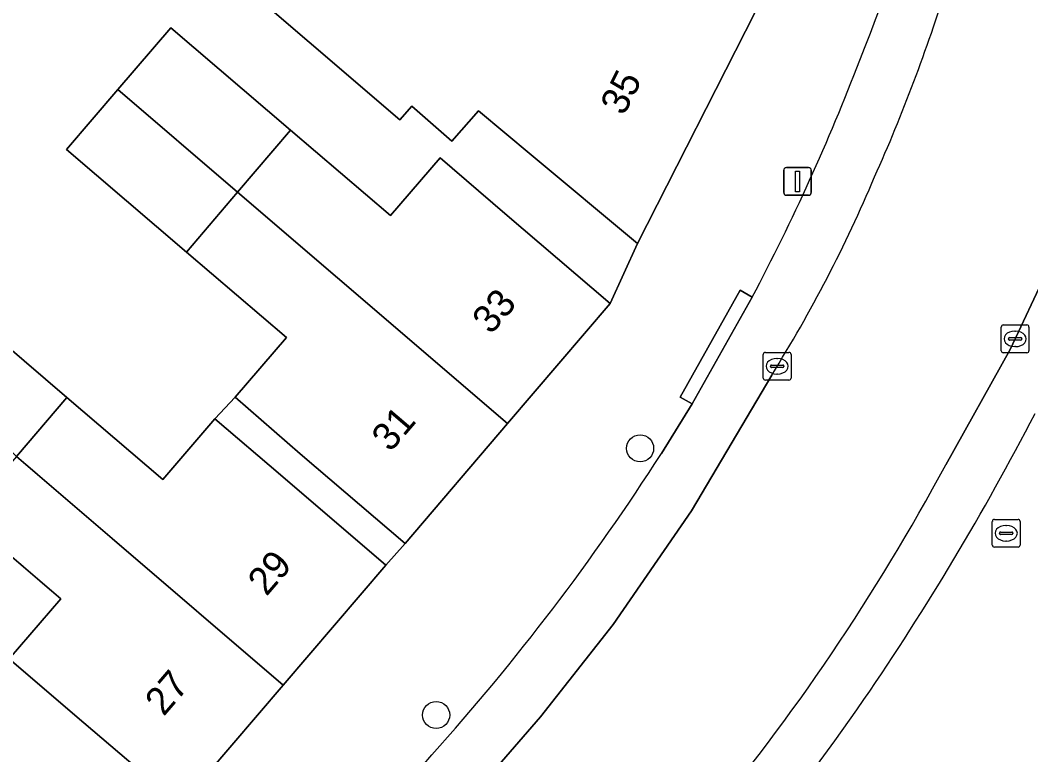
# Model space of a CAD drawing. Extents: x 162879 to 165540, y 384011 to 385181.
# Drawn here: x 164248.79 to 164285.23, y 384359.25 to 384385.74 of the extents above; entities that cross this region are included whole.
import ezdxf

# ---------------------------------------------------------------- set-up
doc = ezdxf.new("R2010")
doc.units = 0
for name, color, linetype in [('IMGEO_Boom', 7, 'Continuous'), ('IMGEO_Erf', 7, 'Continuous'), ('IMGEO_Kolk', 7, 'Continuous'), ('IMGEO_Lichtmast', 7, 'Continuous'), ('IMGEO_Pand', 7, 'Continuous'), ('IMGEO_Pand_nummerreeks', 7, 'Continuous'), ('IMGEO_Pand_overbouw', 7, 'Continuous'), ('IMGEO_Parkeervlak_open', 7, 'Continuous'), ('IMGEO_Rijbaan_lokaal_gesloten', 7, 'Continuous'), ('IMGEO_Rioolput', 7, 'Continuous'), ('IMGEO_Voetpad_open', 7, 'Continuous')]:
    doc.layers.add(name, color=color, linetype=linetype)

msp = doc.modelspace()

# ---------------------------------------------------------------- linework, layer by layer
at = {"layer": 'IMGEO_Boom'}
for centre in [(164271.145, 384370.303), (164263.79, 384360.686)]:
    msp.add_circle(centre, 0.489, dxfattribs=at)
at = {"layer": 'IMGEO_Erf'}
for points in [[(164247.382, 384374.782), (164250.477, 384372.133), (164253.93, 384369.178), (164255.809, 384371.373), (164258.178, 384369.345), (164261.977, 384366.094), (164262.667, 384366.877), (164258.888, 384370.111), (164256.543, 384372.144), (164258.388, 384374.301), (164254.784, 384377.384), (164250.465, 384381.078), (164252.316, 384383.243), (164254.223, 384385.472), (164258.542, 384381.777), (164262.145, 384378.695), (164263.93, 384380.782), (164266.271, 384378.778), (164270.07, 384375.527), (164271.057, 384377.691), (164267.216, 384380.891), (164265.32, 384382.471), (164264.358, 384381.377), (164262.911, 384382.649), (164262.476, 384382.154), (164236.314, 384404.571)], [(164246.201, 384348.47), (164248.925, 384351.39), (164254.565, 384357.434), (164250.766, 384360.685), (164248.397, 384362.714), (164250.251, 384364.881), (164246.799, 384367.836)]]:
    msp.add_lwpolyline(points, dxfattribs=at)
at = {"layer": 'IMGEO_Kolk'}
for p, q in [((164284.168, 384373.826), (164284.168, 384374.678)), ((164284.243, 384374.752), (164285.095, 384374.752)), ((164284.656, 384374.532), (164284.681, 384374.532)), ((164285.169, 384374.678), (164285.169, 384373.826)), ((164284.427, 384374.246), (164284.427, 384374.258)), ((164284.865, 384374.209), (164284.467, 384374.209)), ((164284.47, 384374.295), (164284.868, 384374.295)), ((164284.911, 384374.258), (164284.911, 384374.246)), ((164275.662, 384373.764), (164276.514, 384373.764)), ((164285.095, 384373.752), (164284.243, 384373.752)), ((164284.679, 384373.972), (164284.654, 384373.972)), ((164275.587, 384372.838), (164275.587, 384373.69)), ((164276.075, 384373.544), (164276.1, 384373.544)), ((164276.588, 384373.69), (164276.588, 384372.838)), ((164275.846, 384373.258), (164275.846, 384373.27)), ((164276.284, 384373.221), (164275.886, 384373.221)), ((164275.889, 384373.307), (164276.287, 384373.307)), ((164276.33, 384373.27), (164276.33, 384373.258)), ((164276.514, 384372.764), (164275.662, 384372.764)), ((164276.098, 384372.984), (164276.073, 384372.984))]:
    msp.add_line(p, q, dxfattribs=at)
for points in [[(164284.168, 384373.826), (164284.168, 384374.678)], [(164284.243, 384374.752), (164285.095, 384374.752)], [(164285.169, 384374.678), (164285.169, 384373.826)], [(164275.662, 384373.764), (164276.514, 384373.764)], [(164285.095, 384373.752), (164284.243, 384373.752)], [(164275.587, 384372.838), (164275.587, 384373.69)], [(164276.588, 384373.69), (164276.588, 384372.838)], [(164276.514, 384372.764), (164275.662, 384372.764)]]:
    msp.add_lwpolyline(points, dxfattribs=at)
for centre, radius, start, end in [((164284.245, 384374.676), 0.0765, 91.552, 178.448), ((164284.245, 384374.676), 0.0765, 91.552, 178.448), ((164285.093, 384374.676), 0.0765, 1.552, 88.448), ((164285.093, 384374.676), 0.0765, 1.552, 88.448), ((164284.467, 384374.255), 0.0403, 85.8775, 175.7526), ((164284.464, 384374.245), 0.0366, 178.938, 274.7102), ((164284.868, 384374.252), 0.043, 264.8664, 352.4533), ((164284.872, 384374.257), 0.0386, 1.7309, 96.639), ((164275.664, 384373.688), 0.0765, 91.552, 178.448), ((164275.664, 384373.688), 0.0765, 91.552, 178.448), ((164276.512, 384373.688), 0.0765, 1.552, 88.448), ((164276.512, 384373.688), 0.0765, 1.552, 88.448), ((164284.245, 384373.828), 0.0765, 181.552, 268.448), ((164284.245, 384373.828), 0.0765, 181.552, 268.448), ((164285.093, 384373.828), 0.0765, 271.552, 358.448), ((164285.093, 384373.828), 0.0765, 271.552, 358.448), ((164275.886, 384373.267), 0.0403, 85.8775, 175.7526), ((164275.883, 384373.257), 0.0366, 178.938, 274.7102), ((164276.287, 384373.264), 0.043, 264.8664, 352.4533), ((164276.291, 384373.269), 0.0386, 1.7309, 96.639), ((164275.664, 384372.84), 0.0765, 181.552, 268.448), ((164275.664, 384372.84), 0.0765, 181.552, 268.448), ((164276.512, 384372.84), 0.0765, 271.552, 358.448), ((164276.512, 384372.84), 0.0765, 271.552, 358.448)]:
    msp.add_arc(centre, radius, start, end, dxfattribs=at)
for centre, major_axis, ratio, start_param, end_param in [((164284.655, 384374.252), (-0.387, 0.002), 0.722429, 4.712389, 7.853982), ((164284.68, 384374.252), (-0.39, 0.002), 0.717154, 1.570796, 4.712389), ((164276.074, 384373.264), (-0.387, 0.002), 0.722429, 4.712389, 7.853982), ((164276.099, 384373.264), (-0.39, 0.002), 0.717154, 1.570796, 4.712389)]:
    msp.add_ellipse(centre, major_axis=major_axis, ratio=ratio, start_param=start_param, end_param=end_param, dxfattribs=at)
at = {"layer": 'IMGEO_Lichtmast'}
for p, q in [((164276.326, 384379.53), (164276.326, 384380.33)), ((164276.326, 384380.33), (164276.326, 384379.53)), ((164276.426, 384380.43), (164277.216, 384380.43)), ((164277.216, 384380.43), (164276.426, 384380.43)), ((164277.316, 384380.33), (164277.316, 384379.53)), ((164277.316, 384379.53), (164277.316, 384380.33)), ((164277.216, 384379.43), (164276.426, 384379.43)), ((164276.426, 384379.43), (164277.216, 384379.43))]:
    msp.add_line(p, q, dxfattribs=at)
msp.add_lwpolyline([(164276.746, 384380.305), (164276.896, 384380.305), (164276.896, 384379.555), (164276.746, 384379.555), (164276.746, 384380.305)], dxfattribs=at)
for centre, start, end in [((164276.426, 384380.33), 90, 180), ((164276.426, 384380.33), 90, 180), ((164277.216, 384380.33), 0, 90), ((164277.216, 384380.33), 360, 90), ((164276.426, 384379.53), 180, 270), ((164276.426, 384379.53), 180, 270), ((164277.216, 384379.53), 270, 0), ((164277.216, 384379.53), 270, 0)]:
    msp.add_arc(centre, 0.1, start, end, dxfattribs=at)
at = {"layer": 'IMGEO_Pand'}
for points in [[(164256.673, 384395.931), (164250.35, 384399.543), (164250.13, 384401.017), (164250.096, 384401.244), (164247.628, 384400.874), (164246.84, 384406.136), (164243.286, 384405.608), (164236.314, 384404.571), (164262.476, 384382.154), (164262.911, 384382.649), (164264.358, 384381.377), (164265.32, 384382.471), (164267.216, 384380.891), (164271.057, 384377.691), (164275.297, 384386.032), (164270.84, 384388.297), (164267.582, 384389.953), (164264.99, 384391.271), (164263.541, 384392.007)], [(164252.316, 384383.243), (164256.632, 384379.544), (164258.542, 384381.777), (164254.223, 384385.472)], [(164252.316, 384383.243), (164250.465, 384381.078), (164254.784, 384377.384), (164256.632, 384379.544)], [(164266.271, 384378.778), (164263.93, 384380.782), (164262.145, 384378.695), (164258.542, 384381.777), (164256.632, 384379.544), (164260.233, 384376.458), (164266.367, 384371.201), (164270.07, 384375.527)], [(164260.233, 384376.458), (164256.632, 384379.544), (164254.784, 384377.384), (164258.388, 384374.301), (164256.543, 384372.144), (164258.888, 384370.111), (164262.667, 384366.877), (164266.367, 384371.201)], [(164245.801, 384372.934), (164248.656, 384370.005), (164250.477, 384372.133), (164247.382, 384374.782)], [(164258.178, 384369.345), (164255.809, 384371.373), (164253.93, 384369.178), (164250.477, 384372.133), (164248.656, 384370.005), (164252.106, 384367.048), (164258.271, 384361.764), (164261.977, 384366.094)], [(164252.106, 384367.048), (164248.656, 384370.005), (164246.799, 384367.836), (164250.251, 384364.881), (164248.397, 384362.714), (164250.766, 384360.685), (164254.565, 384357.434), (164258.271, 384361.764)]]:
    msp.add_lwpolyline(points, close=True, dxfattribs=at)
at = {"layer": 'IMGEO_Pand_overbouw'}
msp.add_lwpolyline([(164261.977, 384366.094), (164262.667, 384366.877), (164258.888, 384370.111), (164256.543, 384372.144), (164255.809, 384371.373), (164258.178, 384369.345)], close=True, dxfattribs=at)
at = {"layer": 'IMGEO_Parkeervlak_open'}
for points in [[(164291.262, 384392.931), (164290.958, 384391.829), (164289.066, 384384.974), (164285.827, 384376.709), (164284.485, 384373.867), (164282.166, 384369.713)], [(164275.191, 384375.756), (164273.019, 384371.903), (164271.912, 384370.116)], [(164253.005, 384343.806), (164257.723, 384349.267), (164267.553, 384360.623), (164270.174, 384363.948), (164273.004, 384368.053), (164275.89, 384372.942)]]:
    msp.add_lwpolyline(points, dxfattribs=at)
for centre, radius, start, end in [((164217.448, 384409.096), 66.421, 338.08049, 352.60398), ((164223.121, 384405.367), 61.878, 335.89315, 342.78004), ((164205.303, 384412.609), 79.01, 332.19687, 339.00517), ((164232.446, 384400.029), 51.197, 328.0564, 337.0836), ((164198.31, 384416.62), 98.045, 325.60865, 332.64034), ((164201.046, 384415.505), 84.155, 318.05206, 327.3607), ((164213.099, 384406.795), 78.392, 320.12405, 331.76843), ((164198.944, 384416.783), 97.615, 316.8142, 325.31982)]:
    msp.add_arc(centre, radius, start, end, dxfattribs=at)
at = {"layer": 'IMGEO_Rijbaan_lokaal_gesloten'}
for points in [[(164282.166, 384369.713), (164284.485, 384373.867), (164285.827, 384376.709), (164289.066, 384384.974), (164290.958, 384391.829), (164284.361, 384393.546), (164284.346, 384393.48), (164284.331, 384393.415), (164282.225, 384387.049)], [(164275.89, 384372.942), (164273.004, 384368.053), (164270.174, 384363.948), (164267.553, 384360.623), (164257.723, 384349.267), (164253.005, 384343.806), (164241.966, 384330.855), (164237.473, 384326.052)]]:
    msp.add_lwpolyline(points, dxfattribs=at)
for centre, radius, start, end in [((164223.121, 384405.367), 61.878, 335.89315, 342.78004), ((164232.446, 384400.029), 51.197, 328.0564, 337.0836), ((164213.099, 384406.795), 78.392, 320.12405, 331.76843)]:
    msp.add_arc(centre, radius, start, end, dxfattribs=at)
at = {"layer": 'IMGEO_Rioolput'}
for p, q in [((164283.847, 384366.815), (164283.847, 384367.667)), ((164283.922, 384367.741), (164284.774, 384367.741)), ((164284.848, 384367.667), (164284.848, 384366.815)), ((164284.106, 384367.235), (164284.106, 384367.247)), ((164284.544, 384367.198), (164284.146, 384367.198)), ((164284.149, 384367.284), (164284.547, 384367.284)), ((164284.335, 384367.521), (164284.36, 384367.521)), ((164284.59, 384367.247), (164284.59, 384367.235)), ((164284.358, 384366.961), (164284.333, 384366.961)), ((164284.774, 384366.741), (164283.922, 384366.741))]:
    msp.add_line(p, q, dxfattribs=at)
for points in [[(164283.847, 384366.815), (164283.847, 384367.667)], [(164283.922, 384367.741), (164284.774, 384367.741)], [(164284.848, 384367.667), (164284.848, 384366.815)], [(164284.774, 384366.741), (164283.922, 384366.741)]]:
    msp.add_lwpolyline(points, dxfattribs=at)
for centre, radius, start, end in [((164283.924, 384367.665), 0.0765, 91.552, 178.448), ((164283.924, 384367.665), 0.0765, 91.552, 178.448), ((164284.772, 384367.665), 0.0765, 1.552, 88.448), ((164284.772, 384367.665), 0.0765, 1.552, 88.448), ((164284.146, 384367.244), 0.0403, 85.8775, 175.7526), ((164284.143, 384367.234), 0.0366, 178.938, 274.7102), ((164284.547, 384367.241), 0.043, 264.8664, 352.4533), ((164284.551, 384367.246), 0.0386, 1.7309, 96.639), ((164283.924, 384366.817), 0.0765, 181.552, 268.448), ((164283.924, 384366.817), 0.0765, 181.552, 268.448), ((164284.772, 384366.817), 0.0765, 271.552, 358.448), ((164284.772, 384366.817), 0.0765, 271.552, 358.448)]:
    msp.add_arc(centre, radius, start, end, dxfattribs=at)
for centre, major_axis, ratio, start_param, end_param in [((164284.334, 384367.241), (-0.387, 0.002), 0.722429, 4.712389, 7.853982), ((164284.359, 384367.241), (-0.39, 0.002), 0.717154, 1.570796, 4.712389)]:
    msp.add_ellipse(centre, major_axis=major_axis, ratio=ratio, start_param=start_param, end_param=end_param, dxfattribs=at)
at = {"layer": 'IMGEO_Voetpad_open'}
for points in [[(164279.992, 384411.295), (164279.693, 384409.967), (164278.899, 384400.526), (164278.584, 384396.774), (164278.725, 384396.782), (164277.041, 384389.492), (164276.928, 384389.549), (164275.648, 384387.032), (164275.297, 384386.032), (164271.057, 384377.691), (164270.07, 384375.527), (164266.367, 384371.201), (164262.667, 384366.877), (164261.977, 384366.094), (164258.271, 384361.764), (164254.565, 384357.434), (164248.925, 384351.39), (164253.152, 384347.804), (164255.649, 384350.692), (164256.046, 384350.382), (164256.319, 384350.664), (164263.637, 384359.251)], [(164271.912, 384370.116), (164273.019, 384371.903), (164272.584, 384372.149), (164274.756, 384376.002), (164275.191, 384375.756)]]:
    msp.add_lwpolyline(points, dxfattribs=at)
msp.add_lwpolyline([(164275.191, 384375.756), (164274.756, 384376.002), (164272.584, 384372.149), (164273.019, 384371.903)], close=True, dxfattribs=at)
for centre, radius, start, end in [((164217.448, 384409.096), 66.421, 338.08049, 352.60398), ((164205.303, 384412.609), 79.01, 332.19687, 339.00517), ((164198.31, 384416.62), 98.045, 325.60865, 332.64034), ((164201.046, 384415.505), 84.155, 318.05206, 327.3607), ((164198.944, 384416.783), 97.615, 316.8142, 325.31982)]:
    msp.add_arc(centre, radius, start, end, dxfattribs=at)

# ---------------------------------------------------------------- texts
at = {"layer": 'IMGEO_Pand_nummerreeks'}
for s, rotation, p in [('35', 63.054, (164270.556, 384382.267)), ('33', 49.4405, (164265.767, 384374.375)), ('31', 49.4405, (164262.139, 384370.136)), ('29', 49.4405, (164257.672, 384364.94)), ('27', 49.4405, (164253.966, 384360.61))]:
    msp.add_text(s, height=1, rotation=rotation, dxfattribs=at).set_placement(p)

doc.saveas('drawing.dxf')
